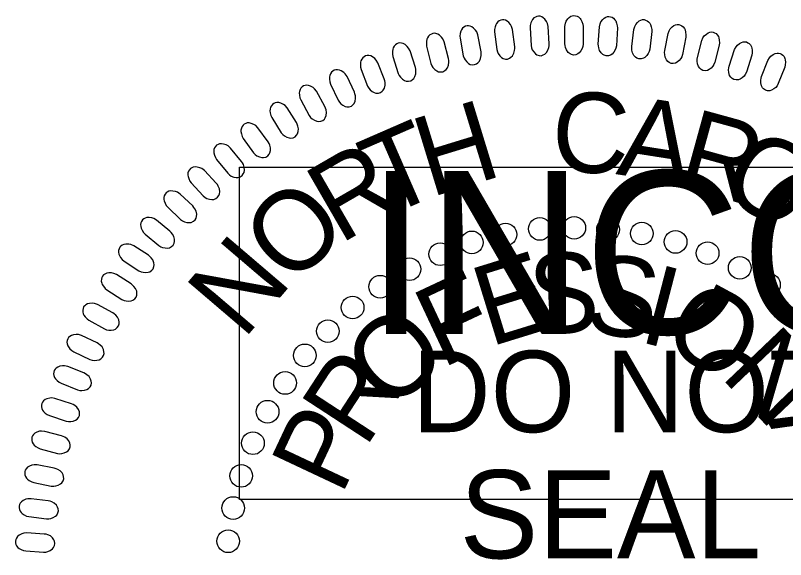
# Model space of a CAD drawing. Extents: x 505602 to 507286, y 483109 to 484209.
# Drawn here: x 507079.7 to 507134.2, y 484098.2 to 484136.7 of the extents above; entities that cross this region are included whole.
import ezdxf

# ---------------------------------------------------------------- set-up
doc = ezdxf.new("R2010")
doc.units = 0
doc.layers.add('Sheet PE Seal Cell', color=7, linetype='Continuous')
doc.layers.add('Sheet Sticker Incomplete CELL', color=7, linetype='Continuous')

msp = doc.modelspace()

# ---------------------------------------------------------------- linework, layer by layer
at = {"layer": 'Sheet PE Seal Cell'}
for points in [[(507115.061, 484134.515), (507114.908, 484135.732), (507114.844, 484135.946), (507114.774, 484136.077), (507114.642, 484136.232), (507114.531, 484136.328), (507114.411, 484136.393), (507114.301, 484136.42), (507114.187, 484136.426), (507114.079, 484136.392), (507113.964, 484136.347), (507113.868, 484136.275), (507113.776, 484136.163), (507113.727, 484136.076), (507113.679, 484135.919), (507113.642, 484135.734), (507113.64, 484135.573), (507113.79, 484134.325), (507113.833, 484134.16), (507113.895, 484134.027), (507114.003, 484133.879), (507114.132, 484133.755), (507114.239, 484133.688), (507114.402, 484133.648), (507114.553, 484133.647), (507114.696, 484133.705), (507114.794, 484133.768), (507114.907, 484133.883), (507115.005, 484134.066), (507115.049, 484134.252), (507115.062, 484134.385)], [(507117.5, 484134.718), (507117.423, 484135.942), (507117.372, 484136.159), (507117.311, 484136.295), (507117.188, 484136.457), (507117.085, 484136.561), (507116.968, 484136.633), (507116.861, 484136.667), (507116.747, 484136.679), (507116.637, 484136.652), (507116.52, 484136.615), (507116.419, 484136.549), (507116.321, 484136.443), (507116.266, 484136.359), (507116.208, 484136.206), (507116.159, 484136.023), (507116.147, 484135.863), (507116.218, 484134.608), (507116.251, 484134.44), (507116.305, 484134.304), (507116.404, 484134.15), (507116.525, 484134.018), (507116.626, 484133.944), (507116.787, 484133.894), (507116.938, 484133.883), (507117.085, 484133.933), (507117.186, 484133.989), (507117.306, 484134.097), (507117.415, 484134.273), (507117.471, 484134.457), (507117.493, 484134.588)], [(507118.615, 484134.727), (507118.615, 484135.953), (507118.653, 484136.173), (507118.705, 484136.313), (507118.817, 484136.482), (507118.915, 484136.592), (507119.027, 484136.672), (507119.131, 484136.711), (507119.244, 484136.731), (507119.355, 484136.711), (507119.475, 484136.682), (507119.58, 484136.622), (507119.684, 484136.522), (507119.744, 484136.442), (507119.811, 484136.292), (507119.871, 484136.113), (507119.894, 484135.953), (507119.901, 484134.697), (507119.878, 484134.527), (507119.833, 484134.388), (507119.744, 484134.228), (507119.631, 484134.088), (507119.534, 484134.009), (507119.377, 484133.949), (507119.228, 484133.929), (507119.078, 484133.969), (507118.974, 484134.019), (507118.846, 484134.118), (507118.727, 484134.288), (507118.66, 484134.468), (507118.63, 484134.598)], [(507120.974, 484134.7), (507121.051, 484135.925), (507121.102, 484136.142), (507121.163, 484136.277), (507121.286, 484136.44), (507121.39, 484136.543), (507121.507, 484136.616), (507121.614, 484136.648), (507121.727, 484136.661), (507121.838, 484136.634), (507121.955, 484136.597), (507122.056, 484136.531), (507122.154, 484136.425), (507122.209, 484136.341), (507122.267, 484136.188), (507122.315, 484136.005), (507122.327, 484135.844), (507122.255, 484134.589), (507122.222, 484134.422), (507122.169, 484134.285), (507122.069, 484134.132), (507121.948, 484134), (507121.846, 484133.926), (507121.686, 484133.876), (507121.535, 484133.865), (507121.389, 484133.915), (507121.287, 484133.972), (507121.167, 484134.079), (507121.059, 484134.255), (507121.002, 484134.439), (507120.981, 484134.57)], [(507123.336, 484134.525), (507123.491, 484135.742), (507123.555, 484135.956), (507123.625, 484136.087), (507123.757, 484136.241), (507123.868, 484136.338), (507123.989, 484136.403), (507124.097, 484136.43), (507124.211, 484136.435), (507124.32, 484136.401), (507124.434, 484136.357), (507124.531, 484136.284), (507124.622, 484136.172), (507124.672, 484136.085), (507124.72, 484135.928), (507124.756, 484135.743), (507124.759, 484135.582), (507124.608, 484134.334), (507124.564, 484134.169), (507124.503, 484134.036), (507124.394, 484133.889), (507124.265, 484133.764), (507124.159, 484133.697), (507123.995, 484133.658), (507123.844, 484133.657), (507123.701, 484133.715), (507123.603, 484133.777), (507123.489, 484133.893), (507123.392, 484134.076), (507123.348, 484134.263), (507123.335, 484134.395)], [(507112.68, 484134.147), (507112.451, 484135.352), (507112.373, 484135.561), (507112.296, 484135.688), (507112.153, 484135.834), (507112.038, 484135.923), (507111.913, 484135.981), (507111.803, 484136), (507111.688, 484135.999), (507111.582, 484135.959), (507111.47, 484135.907), (507111.378, 484135.829), (507111.294, 484135.71), (507111.25, 484135.621), (507111.213, 484135.461), (507111.187, 484135.274), (507111.195, 484135.113), (507111.423, 484133.877), (507111.476, 484133.715), (507111.546, 484133.586), (507111.665, 484133.446), (507111.801, 484133.33), (507111.911, 484133.27), (507112.077, 484133.24), (507112.227, 484133.249), (507112.367, 484133.316), (507112.46, 484133.385), (507112.566, 484133.506), (507112.652, 484133.695), (507112.685, 484133.884), (507112.689, 484134.017)], [(507125.676, 484134.239), (507125.906, 484135.444), (507125.984, 484135.652), (507126.062, 484135.779), (507126.204, 484135.925), (507126.319, 484136.014), (507126.444, 484136.071), (507126.555, 484136.091), (507126.669, 484136.09), (507126.775, 484136.049), (507126.887, 484135.997), (507126.979, 484135.919), (507127.063, 484135.801), (507127.106, 484135.712), (507127.144, 484135.552), (507127.17, 484135.365), (507127.162, 484135.203), (507126.933, 484133.968), (507126.879, 484133.806), (507126.809, 484133.677), (507126.691, 484133.537), (507126.554, 484133.421), (507126.444, 484133.361), (507126.279, 484133.332), (507126.128, 484133.34), (507125.989, 484133.407), (507125.896, 484133.476), (507125.789, 484133.598), (507125.704, 484133.787), (507125.671, 484133.975), (507125.666, 484134.109)], [(507110.375, 484133.675), (507110.07, 484134.863), (507109.98, 484135.066), (507109.894, 484135.189), (507109.743, 484135.325), (507109.622, 484135.407), (507109.494, 484135.457), (507109.382, 484135.47), (507109.269, 484135.461), (507109.165, 484135.414), (507109.057, 484135.355), (507108.97, 484135.271), (507108.893, 484135.148), (507108.855, 484135.057), (507108.827, 484134.895), (507108.814, 484134.706), (507108.832, 484134.546), (507109.137, 484133.327), (507109.2, 484133.168), (507109.279, 484133.044), (507109.405, 484132.912), (507109.549, 484132.804), (507109.662, 484132.752), (507109.83, 484132.732), (507109.979, 484132.75), (507110.114, 484132.826), (507110.203, 484132.9), (507110.301, 484133.028), (507110.375, 484133.222), (507110.396, 484133.413), (507110.392, 484133.545)], [(507127.981, 484133.765), (507128.286, 484134.953), (507128.377, 484135.156), (507128.463, 484135.279), (507128.614, 484135.415), (507128.735, 484135.497), (507128.863, 484135.546), (507128.975, 484135.559), (507129.089, 484135.551), (507129.192, 484135.503), (507129.3, 484135.444), (507129.387, 484135.36), (507129.463, 484135.238), (507129.501, 484135.146), (507129.529, 484134.984), (507129.543, 484134.795), (507129.525, 484134.634), (507129.219, 484133.416), (507129.154, 484133.258), (507129.076, 484133.134), (507128.95, 484133.001), (507128.806, 484132.894), (507128.693, 484132.841), (507128.526, 484132.822), (507128.376, 484132.84), (507128.241, 484132.916), (507128.152, 484132.99), (507128.054, 484133.118), (507127.98, 484133.312), (507127.96, 484133.503), (507127.963, 484133.635)], [(507108.041, 484133.054), (507107.662, 484134.221), (507107.56, 484134.418), (507107.467, 484134.535), (507107.308, 484134.662), (507107.181, 484134.736), (507107.05, 484134.777), (507106.938, 484134.783), (507106.825, 484134.767), (507106.724, 484134.714), (507106.621, 484134.648), (507106.539, 484134.56), (507106.47, 484134.432), (507106.438, 484134.338), (507106.42, 484134.175), (507106.419, 484133.985), (507106.447, 484133.826), (507106.827, 484132.629), (507106.901, 484132.475), (507106.987, 484132.356), (507107.121, 484132.232), (507107.271, 484132.134), (507107.388, 484132.088), (507107.556, 484132.079), (507107.704, 484132.107), (507107.834, 484132.191), (507107.919, 484132.271), (507108.009, 484132.404), (507108.07, 484132.603), (507108.079, 484132.794), (507108.067, 484132.927)], [(507130.231, 484133.143), (507130.61, 484134.31), (507130.714, 484134.507), (507130.807, 484134.623), (507130.966, 484134.75), (507131.092, 484134.824), (507131.223, 484134.866), (507131.335, 484134.871), (507131.448, 484134.855), (507131.549, 484134.801), (507131.653, 484134.736), (507131.735, 484134.647), (507131.803, 484134.52), (507131.835, 484134.425), (507131.853, 484134.262), (507131.854, 484134.073), (507131.826, 484133.914), (507131.444, 484132.717), (507131.371, 484132.562), (507131.285, 484132.444), (507131.15, 484132.319), (507131, 484132.222), (507130.883, 484132.176), (507130.715, 484132.167), (507130.567, 484132.195), (507130.437, 484132.279), (507130.353, 484132.359), (507130.263, 484132.493), (507130.202, 484132.691), (507130.193, 484132.883), (507130.205, 484133.015)], [(507132.514, 484132.408), (507132.966, 484133.548), (507133.082, 484133.739), (507133.182, 484133.849), (507133.349, 484133.966), (507133.48, 484134.032), (507133.613, 484134.065), (507133.725, 484134.063), (507133.837, 484134.041), (507133.933, 484133.981), (507134.034, 484133.909), (507134.109, 484133.814), (507134.17, 484133.683), (507134.196, 484133.587), (507134.203, 484133.423), (507134.193, 484133.234), (507134.155, 484133.078), (507133.699, 484131.906), (507133.615, 484131.757), (507133.522, 484131.644), (507133.38, 484131.529), (507133.224, 484131.44), (507133.105, 484131.402), (507132.936, 484131.404), (507132.79, 484131.441), (507132.666, 484131.533), (507132.587, 484131.618), (507132.505, 484131.757), (507132.457, 484131.959), (507132.46, 484132.151), (507132.481, 484132.282)], [(507105.84, 484132.238), (507105.389, 484133.379), (507105.273, 484133.569), (507105.174, 484133.68), (507105.007, 484133.796), (507104.876, 484133.863), (507104.743, 484133.895), (507104.631, 484133.894), (507104.519, 484133.871), (507104.422, 484133.811), (507104.322, 484133.739), (507104.247, 484133.645), (507104.186, 484133.514), (507104.16, 484133.418), (507104.152, 484133.254), (507104.163, 484133.065), (507104.2, 484132.909), (507104.656, 484131.737), (507104.739, 484131.588), (507104.832, 484131.475), (507104.974, 484131.359), (507105.13, 484131.271), (507105.249, 484131.232), (507105.418, 484131.234), (507105.564, 484131.271), (507105.688, 484131.363), (507105.767, 484131.448), (507105.849, 484131.587), (507105.898, 484131.789), (507105.894, 484131.981), (507105.874, 484132.112)], [(507103.723, 484131.305), (507103.201, 484132.415), (507103.074, 484132.598), (507102.967, 484132.702), (507102.794, 484132.808), (507102.659, 484132.866), (507102.523, 484132.89), (507102.412, 484132.882), (507102.302, 484132.852), (507102.209, 484132.786), (507102.113, 484132.709), (507102.044, 484132.61), (507101.992, 484132.475), (507101.972, 484132.378), (507101.974, 484132.213), (507101.997, 484132.025), (507102.044, 484131.871), (507102.572, 484130.732), (507102.665, 484130.587), (507102.765, 484130.48), (507102.914, 484130.374), (507103.075, 484130.295), (507103.196, 484130.265), (507103.364, 484130.277), (507103.508, 484130.322), (507103.626, 484130.422), (507103.7, 484130.512), (507103.772, 484130.656), (507103.808, 484130.86), (507103.793, 484131.051), (507103.765, 484131.182)], [(507101.64, 484130.291), (507101.049, 484131.367), (507100.911, 484131.541), (507100.798, 484131.638), (507100.618, 484131.733), (507100.48, 484131.782), (507100.343, 484131.798), (507100.233, 484131.783), (507100.124, 484131.746), (507100.036, 484131.675), (507099.945, 484131.591), (507099.882, 484131.488), (507099.839, 484131.35), (507099.825, 484131.251), (507099.837, 484131.088), (507099.872, 484130.901), (507099.929, 484130.751), (507100.528, 484129.646), (507100.628, 484129.508), (507100.735, 484129.408), (507100.89, 484129.311), (507101.056, 484129.242), (507101.18, 484129.219), (507101.346, 484129.242), (507101.486, 484129.297), (507101.599, 484129.404), (507101.666, 484129.498), (507101.73, 484129.647), (507101.753, 484129.853), (507101.726, 484130.043), (507101.689, 484130.17)], [(507099.622, 484129.149), (507098.965, 484130.185), (507098.816, 484130.351), (507098.698, 484130.44), (507098.512, 484130.524), (507098.371, 484130.564), (507098.234, 484130.572), (507098.124, 484130.549), (507098.019, 484130.506), (507097.934, 484130.429), (507097.85, 484130.34), (507097.793, 484130.234), (507097.758, 484130.093), (507097.751, 484129.994), (507097.774, 484129.831), (507097.82, 484129.648), (507097.886, 484129.5), (507098.553, 484128.435), (507098.662, 484128.304), (507098.775, 484128.21), (507098.937, 484128.124), (507099.106, 484128.066), (507099.23, 484128.05), (507099.395, 484128.084), (507099.532, 484128.147), (507099.637, 484128.261), (507099.699, 484128.359), (507099.753, 484128.511), (507099.763, 484128.719), (507099.723, 484128.907), (507099.679, 484129.032)], [(507097.622, 484127.795), (507096.901, 484128.787), (507096.742, 484128.943), (507096.618, 484129.026), (507096.427, 484129.097), (507096.284, 484129.128), (507096.147, 484129.127), (507096.038, 484129.098), (507095.936, 484129.048), (507095.857, 484128.966), (507095.778, 484128.872), (507095.728, 484128.762), (507095.702, 484128.619), (507095.7, 484128.52), (507095.734, 484128.359), (507095.791, 484128.179), (507095.867, 484128.037), (507096.599, 484127.015), (507096.717, 484126.891), (507096.835, 484126.804), (507097.001, 484126.728), (507097.174, 484126.681), (507097.3, 484126.673), (507097.462, 484126.717), (507097.594, 484126.789), (507097.692, 484126.909), (507097.747, 484127.011), (507097.792, 484127.166), (507097.789, 484127.374), (507097.738, 484127.559), (507097.686, 484127.681)], [(507095.741, 484126.406), (507094.959, 484127.351), (507094.791, 484127.496), (507094.662, 484127.571), (507094.468, 484127.63), (507094.323, 484127.653), (507094.185, 484127.643), (507094.08, 484127.606), (507093.98, 484127.55), (507093.906, 484127.463), (507093.834, 484127.364), (507093.79, 484127.252), (507093.774, 484127.108), (507093.778, 484127.008), (507093.822, 484126.85), (507093.89, 484126.674), (507093.975, 484126.536), (507094.769, 484125.563), (507094.895, 484125.447), (507095.018, 484125.368), (507095.189, 484125.302), (507095.364, 484125.266), (507095.49, 484125.266), (507095.649, 484125.32), (507095.777, 484125.4), (507095.867, 484125.526), (507095.916, 484125.631), (507095.95, 484125.789), (507095.934, 484125.996), (507095.872, 484126.177), (507095.812, 484126.296)], [(507093.954, 484124.866), (507093.114, 484125.761), (507092.937, 484125.896), (507092.803, 484125.962), (507092.605, 484126.009), (507092.46, 484126.022), (507092.323, 484126.004), (507092.219, 484125.961), (507092.124, 484125.899), (507092.056, 484125.808), (507091.989, 484125.704), (507091.954, 484125.589), (507091.946, 484125.444), (507091.956, 484125.345), (507092.01, 484125.19), (507092.089, 484125.018), (507092.181, 484124.887), (507093.037, 484123.965), (507093.169, 484123.857), (507093.297, 484123.786), (507093.472, 484123.731), (507093.65, 484123.705), (507093.775, 484123.713), (507093.93, 484123.778), (507094.053, 484123.866), (507094.134, 484123.997), (507094.177, 484124.105), (507094.201, 484124.265), (507094.173, 484124.47), (507094.098, 484124.647), (507094.032, 484124.762)], [(507092.291, 484123.257), (507091.398, 484124.097), (507091.212, 484124.22), (507091.074, 484124.278), (507090.874, 484124.312), (507090.728, 484124.317), (507090.592, 484124.29), (507090.492, 484124.241), (507090.401, 484124.173), (507090.339, 484124.078), (507090.278, 484123.969), (507090.25, 484123.853), (507090.251, 484123.708), (507090.268, 484123.61), (507090.331, 484123.458), (507090.421, 484123.292), (507090.522, 484123.165), (507091.433, 484122.3), (507091.571, 484122.2), (507091.704, 484122.137), (507091.882, 484122.093), (507092.06, 484122.08), (507092.185, 484122.095), (507092.336, 484122.169), (507092.453, 484122.264), (507092.526, 484122.401), (507092.561, 484122.511), (507092.576, 484122.672), (507092.534, 484122.875), (507092.45, 484123.047), (507092.376, 484123.157)], [(507090.678, 484121.471), (507089.733, 484122.253), (507089.54, 484122.364), (507089.399, 484122.413), (507089.197, 484122.435), (507089.051, 484122.43), (507088.918, 484122.394), (507088.821, 484122.339), (507088.734, 484122.265), (507088.677, 484122.166), (507088.625, 484122.055), (507088.603, 484121.936), (507088.614, 484121.792), (507088.637, 484121.695), (507088.709, 484121.548), (507088.81, 484121.387), (507088.918, 484121.268), (507089.881, 484120.461), (507090.026, 484120.37), (507090.162, 484120.316), (507090.343, 484120.283), (507090.521, 484120.28), (507090.645, 484120.305), (507090.791, 484120.387), (507090.901, 484120.489), (507090.966, 484120.63), (507090.995, 484120.743), (507090.999, 484120.904), (507090.945, 484121.104), (507090.849, 484121.271), (507090.768, 484121.376)], [(507089.153, 484119.768), (507088.123, 484120.434), (507087.918, 484120.521), (507087.773, 484120.554), (507087.57, 484120.552), (507087.425, 484120.529), (507087.297, 484120.478), (507087.207, 484120.412), (507087.129, 484120.329), (507087.085, 484120.224), (507087.046, 484120.107), (507087.038, 484119.987), (507087.066, 484119.845), (507087.1, 484119.751), (507087.189, 484119.614), (507087.308, 484119.465), (507087.429, 484119.36), (507088.481, 484118.672), (507088.635, 484118.599), (507088.777, 484118.561), (507088.96, 484118.55), (507089.138, 484118.568), (507089.258, 484118.607), (507089.393, 484118.706), (507089.491, 484118.82), (507089.538, 484118.968), (507089.553, 484119.083), (507089.539, 484119.244), (507089.461, 484119.436), (507089.347, 484119.59), (507089.254, 484119.685)], [(507087.939, 484117.746), (507086.904, 484118.403), (507086.699, 484118.489), (507086.553, 484118.52), (507086.349, 484118.517), (507086.204, 484118.493), (507086.077, 484118.441), (507085.987, 484118.374), (507085.91, 484118.29), (507085.867, 484118.184), (507085.828, 484118.068), (507085.822, 484117.947), (507085.851, 484117.806), (507085.886, 484117.712), (507085.976, 484117.575), (507086.095, 484117.428), (507086.218, 484117.324), (507087.275, 484116.644), (507087.43, 484116.572), (507087.572, 484116.535), (507087.755, 484116.525), (507087.933, 484116.545), (507088.052, 484116.584), (507088.187, 484116.685), (507088.284, 484116.801), (507088.33, 484116.948), (507088.344, 484117.063), (507088.328, 484117.224), (507088.25, 484117.415), (507088.134, 484117.569), (507088.04, 484117.664)], [(507086.636, 484115.696), (507085.561, 484116.288), (507085.351, 484116.361), (507085.203, 484116.382), (507085, 484116.366), (507084.857, 484116.333), (507084.733, 484116.274), (507084.648, 484116.201), (507084.576, 484116.113), (507084.54, 484116.005), (507084.509, 484115.886), (507084.51, 484115.765), (507084.548, 484115.626), (507084.589, 484115.535), (507084.687, 484115.403), (507084.816, 484115.264), (507084.945, 484115.168), (507086.042, 484114.556), (507086.201, 484114.493), (507086.345, 484114.466), (507086.528, 484114.467), (507086.705, 484114.498), (507086.822, 484114.545), (507086.95, 484114.653), (507087.039, 484114.775), (507087.076, 484114.925), (507087.083, 484115.04), (507087.057, 484115.2), (507086.966, 484115.386), (507086.841, 484115.532), (507086.742, 484115.621)], [(507085.527, 484113.572), (507084.417, 484114.095), (507084.203, 484114.155), (507084.054, 484114.167), (507083.853, 484114.138), (507083.712, 484114.097), (507083.592, 484114.029), (507083.511, 484113.951), (507083.446, 484113.858), (507083.416, 484113.749), (507083.392, 484113.627), (507083.401, 484113.508), (507083.447, 484113.371), (507083.494, 484113.283), (507083.601, 484113.158), (507083.738, 484113.027), (507083.872, 484112.938), (507085.007, 484112.396), (507085.169, 484112.345), (507085.314, 484112.326), (507085.497, 484112.339), (507085.671, 484112.381), (507085.784, 484112.435), (507085.906, 484112.551), (507085.988, 484112.678), (507086.015, 484112.83), (507086.014, 484112.947), (507085.978, 484113.104), (507085.876, 484113.284), (507085.742, 484113.421), (507085.637, 484113.504)], [(507084.587, 484111.454), (507083.447, 484111.905), (507083.229, 484111.951), (507083.08, 484111.955), (507082.881, 484111.913), (507082.743, 484111.863), (507082.628, 484111.788), (507082.553, 484111.705), (507082.492, 484111.608), (507082.47, 484111.497), (507082.454, 484111.374), (507082.47, 484111.255), (507082.525, 484111.122), (507082.577, 484111.036), (507082.691, 484110.918), (507082.836, 484110.797), (507082.976, 484110.717), (507084.141, 484110.247), (507084.307, 484110.206), (507084.454, 484110.196), (507084.635, 484110.22), (507084.806, 484110.273), (507084.916, 484110.334), (507085.03, 484110.458), (507085.103, 484110.589), (507085.121, 484110.743), (507085.113, 484110.859), (507085.068, 484111.014), (507084.954, 484111.187), (507084.812, 484111.316), (507084.702, 484111.392)], [(507083.712, 484109.264), (507082.545, 484109.644), (507082.325, 484109.676), (507082.176, 484109.67), (507081.98, 484109.616), (507081.845, 484109.557), (507081.735, 484109.475), (507081.665, 484109.388), (507081.611, 484109.287), (507081.596, 484109.175), (507081.587, 484109.052), (507081.611, 484108.934), (507081.674, 484108.803), (507081.732, 484108.722), (507081.853, 484108.611), (507082.005, 484108.499), (507082.15, 484108.428), (507083.342, 484108.032), (507083.51, 484108.001), (507083.657, 484108.001), (507083.837, 484108.037), (507084.004, 484108.101), (507084.111, 484108.168), (507084.216, 484108.298), (507084.281, 484108.435), (507084.289, 484108.589), (507084.274, 484108.704), (507084.219, 484108.856), (507084.094, 484109.022), (507083.944, 484109.142), (507083.83, 484109.21)], [(507083.007, 484107.009), (507081.819, 484107.314), (507081.598, 484107.332), (507081.449, 484107.317), (507081.257, 484107.25), (507081.126, 484107.184), (507081.021, 484107.095), (507080.957, 484107.003), (507080.909, 484106.9), (507080.9, 484106.787), (507080.9, 484106.663), (507080.931, 484106.546), (507081.002, 484106.421), (507081.064, 484106.343), (507081.193, 484106.24), (507081.352, 484106.138), (507081.501, 484106.076), (507082.716, 484105.756), (507082.886, 484105.736), (507083.032, 484105.744), (507083.209, 484105.792), (507083.372, 484105.865), (507083.474, 484105.94), (507083.571, 484106.077), (507083.627, 484106.217), (507083.626, 484106.371), (507083.603, 484106.485), (507083.539, 484106.633), (507083.404, 484106.791), (507083.247, 484106.901), (507083.128, 484106.962)], [(507082.496, 484104.713), (507081.291, 484104.943), (507081.069, 484104.948), (507080.921, 484104.923), (507080.734, 484104.844), (507080.608, 484104.77), (507080.508, 484104.674), (507080.45, 484104.579), (507080.409, 484104.473), (507080.408, 484104.359), (507080.415, 484104.236), (507080.453, 484104.122), (507080.532, 484104.001), (507080.599, 484103.927), (507080.733, 484103.832), (507080.899, 484103.74), (507081.051, 484103.688), (507082.284, 484103.444), (507082.455, 484103.435), (507082.601, 484103.453), (507082.774, 484103.511), (507082.932, 484103.595), (507083.029, 484103.676), (507083.117, 484103.818), (507083.165, 484103.962), (507083.154, 484104.116), (507083.124, 484104.228), (507083.05, 484104.372), (507082.906, 484104.521), (507082.742, 484104.621), (507082.62, 484104.674)], [(507082.076, 484102.399), (507080.859, 484102.553), (507080.636, 484102.543), (507080.491, 484102.51), (507080.309, 484102.419), (507080.187, 484102.337), (507080.094, 484102.236), (507080.042, 484102.137), (507080.008, 484102.028), (507080.014, 484101.914), (507080.028, 484101.792), (507080.074, 484101.68), (507080.161, 484101.564), (507080.232, 484101.495), (507080.372, 484101.409), (507080.542, 484101.327), (507080.698, 484101.285), (507081.944, 484101.12), (507082.115, 484101.121), (507082.259, 484101.148), (507082.428, 484101.216), (507082.581, 484101.31), (507082.672, 484101.397), (507082.752, 484101.545), (507082.79, 484101.691), (507082.769, 484101.844), (507082.733, 484101.954), (507082.65, 484102.093), (507082.497, 484102.232), (507082.327, 484102.322), (507082.202, 484102.368)], [(507081.789, 484100.055), (507080.565, 484100.132), (507080.343, 484100.109), (507080.2, 484100.066), (507080.024, 484099.965), (507079.908, 484099.874), (507079.822, 484099.768), (507079.776, 484099.666), (507079.749, 484099.555), (507079.762, 484099.442), (507079.784, 484099.32), (507079.837, 484099.212), (507079.93, 484099.102), (507080.006, 484099.037), (507080.151, 484098.96), (507080.326, 484098.889), (507080.484, 484098.857), (507081.738, 484098.77), (507081.908, 484098.781), (507082.05, 484098.818), (507082.215, 484098.897), (507082.362, 484099), (507082.448, 484099.092), (507082.517, 484099.245), (507082.546, 484099.393), (507082.516, 484099.544), (507082.473, 484099.652), (507082.382, 484099.785), (507082.22, 484099.915), (507082.045, 484099.994), (507081.917, 484100.032)]]:
    msp.add_lwpolyline(points, close=True, dxfattribs=at)
for centre in [(507116.843, 484121.631), (507119.272, 484121.71), (507121.661, 484121.59), (507124.049, 484121.31), (507114.414, 484121.234), (507112.025, 484120.677), (507126.438, 484120.712), (507109.796, 484119.841), (507128.707, 484119.914), (507107.621, 484118.78), (507130.976, 484118.878), (507105.55, 484117.546), (507133.046, 484117.682), (507103.599, 484116.072), (507101.847, 484114.4), (507100.214, 484112.687), (507098.82, 484110.736), (507097.585, 484108.705), (507096.549, 484106.474), (507095.712, 484104.164), (507095.154, 484101.893), (507094.795, 484099.543)]:
    msp.add_circle(centre, 0.801, dxfattribs=at)
at = {"layer": 'Sheet Sticker Incomplete CELL'}
msp.add_lwpolyline([(507095.597, 484102.505), (507095.597, 484126.005), (507242.597, 484126.005), (507242.597, 484102.505)], close=True, dxfattribs=at)

# ---------------------------------------------------------------- texts
at = {"layer": 'Sheet PE Seal Cell'}
for s, height, rotation, p in [('C', 5.669, 357.5877, (507117.59, 484125.721)), ('A', 5.669, 351.0983, (507122.165, 484125.513)), ('H', 5.669, 17.0557, (507109.084, 484123.838)), ('R', 5.669, 344.609, (507126.371, 484124.719)), ('T', 5.669, 23.5451, (507105.906, 484122.428)), ('O', 5.669, 331.6302, (507129.326, 484124.065)), ('R', 5.669, 30.0345, (507102.685, 484120.509)), ('O', 5.669, 43.0132, (507099.209, 484117.481)), ('N', 5.669, 49.5025, (507095.863, 484113.726)), ('E', 5.669, 17.1686, (507113.281, 484113.269)), ('S', 5.669, 1.289, (507116.048, 484114.229)), ('S', 5.669, 353.3492, (507119.909, 484114.33)), ('I', 5.669, 345.4094, (507123.709, 484113.698)), ('F', 5.669, 25.1084, (507109.891, 484111.73)), ('O', 5.669, 329.5298, (507125.213, 484113.526)), ('O', 5.669, 40.988, (507106.194, 484108.592)), ('N', 5.669, 313.6502, (507129.525, 484111.222)), ('R', 5.669, 56.8676, (507104.48, 484106.046)), ('P', 5.669, 64.8074, (507102.793, 484102.684)), ('A', 5.669, 297.7707, (507132.862, 484108.141)), ('SEAL', 6.2363, 359.9814, (507111.164, 484098.335))]:
    msp.add_text(s, height=height, rotation=rotation, dxfattribs=at).set_placement(p)
at = {"layer": 'Sheet Sticker Incomplete CELL'}
for s, height, p in [('INCOMPLETE PLANS', 11.52, (507104.547, 484114.205)), ('DO NOT USE FOR R/W ACQUISITION', 5.76, (507107.797, 484107.255))]:
    msp.add_text(s, height=height, dxfattribs=at).set_placement(p)

doc.saveas('drawing.dxf')
